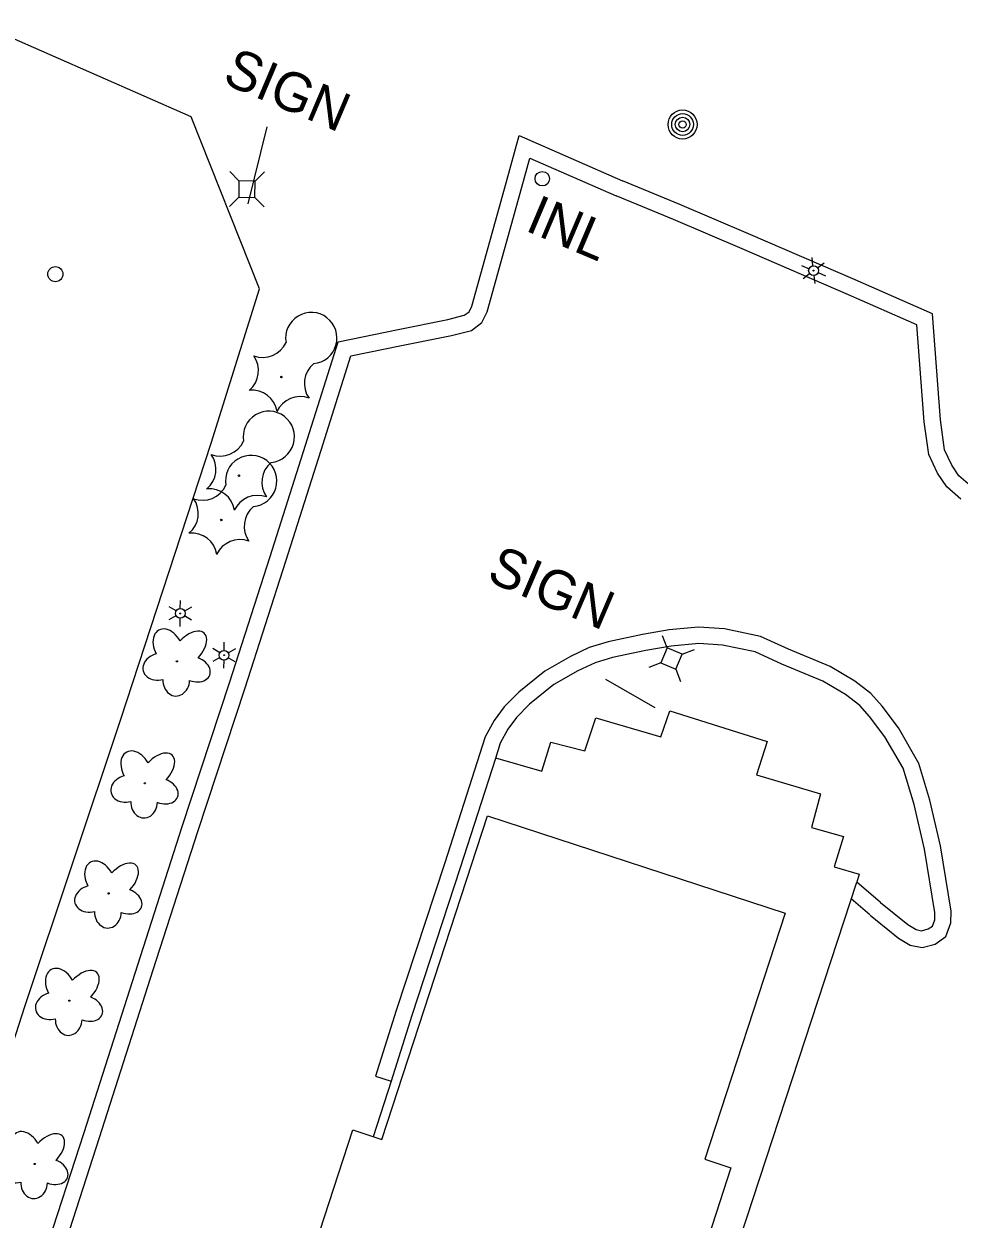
# Model space of a CAD drawing. Extents: x 588843 to 2552415, y 180129 to 269402.
# Drawn here: x 593101.4 to 593244.8, y 185579.7 to 185762.9 of the extents above; entities that cross this region are included whole.
import ezdxf

# ---------------------------------------------------------------- set-up
doc = ezdxf.new("R2010")
doc.units = 0
for name, color, linetype in [('Default', 7, 'Continuous'), ('E_BLD', 7, 'Continuous'), ('E_DRN', 7, 'Continuous'), ('E_DRN_Text', 7, 'Continuous'), ('E_DWY', 7, 'Continuous'), ('E_LAND_Vegetation', 7, 'Continuous'), ('E_LTG', 7, 'Continuous'), ('E_MISCPROP', 7, 'Continuous'), ('E_PATH_Sidewalk', 7, 'Continuous'), ('E_SGN', 7, 'Continuous'), ('E_SGN_Text', 7, 'Continuous'), ('E_UTL_AG_Bold', 7, 'Continuous')]:
    doc.layers.add(name, color=color, linetype=linetype)

# ---------------------------------------------------------------- blocks, each defined once
blk = doc.blocks.new('LPOL')
at = {"layer": 'Default'}
for p, q in [((-4, 0), (-1.5, 0)), ((-0.75, 1.3), (-2, 3.46)), ((0.75, 1.3), (2, 3.46)), ((1.5, 0), (4, 0)), ((-2, -3.46), (-0.75, -1.3)), ((2, -3.46), (0.75, -1.3))]:
    blk.add_line(p, q, dxfattribs=at)
for radius in [1.5, 1.5, 1.5, 0.125]:
    blk.add_circle((0, 0), radius, dxfattribs=at)
blk = doc.blocks.new('POLE')
at = {"layer": 'Default'}
for radius in [4.46, 3.35, 2.23, 1.12]:
    blk.add_circle((0, 0), radius, dxfattribs=at)
blk = doc.blocks.new('DTRE')
at = {"layer": 'Default'}
blk.add_circle((-0.18, 0), 0.183, dxfattribs=at)
for centre, major_axis, ratio in [((-1.87, 5.32), (1.36, -4.98), 0.782863), ((4.06, 2.74), (-5.27, -2.93), 0.691916), ((-5.87, 0.15), (4.93, -0.12), 0.832022), ((3.54, -3.71), (-5.01, 4.58), 0.560249), ((-2.49, -5.24), (1.8, 4.86), 0.716896)]:
    blk.add_ellipse(centre, major_axis=major_axis, ratio=ratio, start_param=1.570796, end_param=4.712389, dxfattribs=at)
blk = doc.blocks.new('CTRE')
at = {"layer": 'Default'}
blk.add_circle((0, 0), 0.223, dxfattribs=at)
for centre, start, end in [((-11.97, 8.96), 280.2067, 5.9716), ((1.81, 14.92), 220.2113, 305.9762), ((13.83, 5.89), 160.2113, 245.9762), ((-13.83, -5.9), 340.2113, 65.9762), ((12.03, -9.04), 185.9272, 100.2511), ((-1.81, -14.93), 40.2113, 125.9762)]:
    blk.add_arc(centre, 7.87, start, end, dxfattribs=at)
blk = doc.blocks.new('PED')
at = {"layer": 'Default'}
for p, q in [((-2.5, 2.5), (-5.33, 5.33)), ((2.5, 2.5), (5.33, 5.33)), ((-2.5, -2.5), (-5.33, -5.33)), ((2.5, -2.5), (5.33, -5.33))]:
    blk.add_line(p, q, dxfattribs=at)
blk.add_lwpolyline([(-2.5, -2.5), (2.5, -2.5), (2.5, 2.5), (-2.5, 2.5)], close=True, dxfattribs=at)
blk = doc.blocks.new('SIGN')
at = {"layer": 'Default'}
blk.add_text('SIGN', height=12, dxfattribs=at).set_placement((-18.55, -6))
blk = doc.blocks.new('INLT_41')
at = {"layer": 'E_DRN_Text'}
blk.add_text('INL', height=12, dxfattribs=at).set_placement((-11.03, -6))

msp = doc.modelspace()

# ---------------------------------------------------------------- linework, layer by layer
at = {"layer": 'E_BLD'}
msp.add_lwpolyline([(593172.43, 185641.5), (593218.07, 185626.6), (593205.76, 185588.9), (593209.78, 185587.59), (593205.14, 185573.36), (593201.06, 185574.69), (593188.55, 185536.35), (593183.23, 185538.09), (593178.68, 185524.15), (593161.23, 185529.85), (593165.83, 185543.96), (593141.48, 185551.91), (593148.16, 185572.38), (593145.24, 185573.33), (593151.78, 185593.37), (593156.24, 185591.91), (593172.43, 185641.5)], close=True, dxfattribs=at)
at = {"layer": 'E_DRN'}
for centre, radius in [((593180.85, 185739.19), 1.11), ((593106.19, 185724.56), 1.16)]:
    msp.add_circle(centre, radius, dxfattribs=at)
at = {"layer": 'E_DWY'}
for points in [[(593073.08, 185519.95), (593085.72, 185563.37), (593101.57, 185612.44), (593116.25, 185656.35), (593130.07, 185698.66), (593137.48, 185722.33), (593127, 185748.67), (593098.2, 185761.32), (593068.93, 185774.26), (593037.36, 185788.12), (593004.66, 185802.42), (592980.13, 185813.54), (592966.01, 185781.91), (592962.98, 185775.38), (592961.51, 185773.47), (592960.45, 185773.06), (592958.78, 185772.92), (592956.88, 185773.45), (592953.94, 185774.8), (592950.49, 185776.9)], [(593099.66, 185558.64), (593104.55, 185574.28), (593110.6, 185592.99), (593118.81, 185618.67), (593125.63, 185639.88), (593132.9, 185661.93), (593139.15, 185681.3), (593144.55, 185698.36), (593149.57, 185714.18), (593158.77, 185716.06), (593166.35, 185717.61), (593168.89, 185718.25), (593169.64, 185718.79), (593170.07, 185719.66), (593175.31, 185738.56), (593177.28, 185745.82), (593193.15, 185738.86)], [(593096.04, 185539.11), (593102.05, 185557.89), (593106.93, 185573.52), (593112.98, 185592.23), (593121.19, 185617.91), (593128.01, 185639.11), (593135.28, 185661.15), (593141.53, 185680.54), (593146.93, 185697.6), (593151.51, 185712.02), (593159.27, 185713.61), (593166.91, 185715.17), (593169.97, 185715.94), (593171.6, 185717.13), (593172.41, 185718.76), (593177.72, 185737.9), (593178.93, 185742.36), (593192.2, 185736.55)], [(593246.52, 185692.09), (593244.74, 185693.64), (593243.62, 185695.28), (593242.54, 185697.61), (593241.89, 185702.21), (593240.68, 185718.47), (593228.82, 185723.69), (593212.46, 185730.72), (593201.96, 185735.22), (593193.15, 185738.86)], [(593245.04, 185690.06), (593242.85, 185691.97), (593241.44, 185694.05), (593240.11, 185696.9), (593239.41, 185701.94), (593238.3, 185716.79), (593227.82, 185721.4), (593211.47, 185728.42), (593200.99, 185732.92), (593192.2, 185736.55)], [(593238.56, 185649.54), (593235.45, 185655.01), (593232.96, 185658.34), (593231.23, 185660.26), (593228.76, 185662.18), (593224.98, 185664.42), (593218.58, 185667.07), (593214.28, 185669.03), (593208.81, 185670.18), (593204.8, 185670.45), (593200.28, 185670.02), (593196.23, 185669.33), (593190.97, 185668.21), (593188.05, 185667.31), (593185.15, 185665.96), (593181.22, 185663.71), (593177.23, 185660.5), (593175.01, 185658.24), (593173.47, 185656.16), (593172.08, 185653.64), (593171.27, 185651.07), (593165.91, 185634.32), (593158.46, 185611.69), (593155.29, 185601.6)], [(593236.17, 185648.81), (593233.37, 185653.61), (593231.03, 185656.75), (593229.52, 185658.43), (593227.35, 185660.11), (593223.86, 185662.18), (593217.59, 185664.78), (593213.49, 185666.64), (593208.47, 185667.69), (593204.83, 185667.94), (593200.61, 185667.54), (593196.7, 185666.87), (593191.6, 185665.79), (593188.95, 185664.97), (593186.3, 185663.74), (593182.64, 185661.64), (593178.91, 185658.65), (593176.91, 185656.61), (593175.58, 185654.8), (593174.39, 185652.65), (593173.66, 185650.32), (593168.28, 185633.55), (593160.84, 185610.92), (593157.68, 185600.85)], [(593231.1, 185626.32), (593235.44, 185622.79), (593237.27, 185621.72), (593239.07, 185621.36), (593241.07, 185621.87), (593242.74, 185623.02), (593243.51, 185625.11), (593243.54, 185626.9), (593241.89, 185636.92), (593240.27, 185643.93), (593238.56, 185649.54)], [(593232.68, 185628.26), (593236.87, 185624.85), (593238.17, 185624.09), (593239, 185623.92), (593240.02, 185624.18), (593240.67, 185624.62), (593241.01, 185625.58), (593241.04, 185626.72), (593239.44, 185636.43), (593237.85, 185643.28), (593236.17, 185648.81)], [(593176.8, 185473.48), (593189.83, 185511.82), (593203.12, 185552.15), (593220.18, 185604.24), (593229.08, 185631.35)], [(593232.68, 185628.26), (593229.08, 185631.35)], [(593231.05, 185626.36), (593228.23, 185628.78)], [(593155.29, 185601.6), (593157.68, 185600.85), (593154.94, 185592.34)]]:
    msp.add_lwpolyline(points, dxfattribs=at)
at = {"layer": 'E_PATH_Sidewalk'}
msp.add_lwpolyline([(593173.69, 185650.43), (593180.8, 185648.37), (593182.15, 185652.81), (593187.38, 185651.51), (593189.04, 185656.55), (593199.02, 185653.64), (593200.42, 185657.62), (593215.33, 185652.92), (593213.7, 185647.8), (593223.48, 185644.92), (593222.1, 185639.74), (593227.03, 185638.38), (593225.59, 185633.7), (593229.42, 185632.57), (593229.08, 185631.35)], dxfattribs=at)
at = {"layer": 'E_SGN'}
for points in [[(593135.76, 185735.33), (593138.65, 185747.16)], [(593198.18, 185658.1), (593190.57, 185662.41)]]:
    msp.add_lwpolyline(points, dxfattribs=at)

# ---------------------------------------------------------------- block references
at = {"layer": 'E_DRN_Text', "xscale": 0.4999999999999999, "yscale": 0.5, "rotation": -22.99539777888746}
msp.add_blockref('INLT_41', (593184.29, 185731.92), dxfattribs=at)
at = {"layer": 'E_LAND_Vegetation', "xscale": 0.5000000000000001, "yscale": 0.5, "rotation": 89.39188762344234}
for name, p in [('CTRE', (593140.85, 185708.79)), ('CTRE', (593134.33, 185693.66)), ('CTRE', (593131.62, 185686.88)), ('DTRE', (593124.83, 185665.29)), ('DTRE', (593119.91, 185646.6)), ('DTRE', (593114.36, 185629.72)), ('DTRE', (593108.34, 185613.27)), ('DTRE', (593103.03, 185588.25))]:
    msp.add_blockref(name, p, dxfattribs=at)
at = {"layer": 'E_LTG'}
for p, xscale, yscale, rotation in [((593222.44, 185725.1), 0.4999999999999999, 0.4999999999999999, -23.35379701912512), ((593125.34, 185672.55), 0.5000000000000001, 0.5, 89.39188762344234), ((593132.06, 185666.14), 0.5000000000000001, 0.5, 89.39188762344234)]:
    msp.add_blockref('LPOL', p, dxfattribs=dict(at, xscale=xscale, yscale=yscale, rotation=rotation))
at = {"layer": 'E_MISCPROP', "xscale": 0.4999999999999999, "yscale": 0.4999999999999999, "rotation": -23.35379701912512}
msp.add_blockref('POLE', (593202.36, 185747.5), dxfattribs=at)
at = {"layer": 'E_SGN_Text', "yscale": 0.5}
for p, xscale, rotation in [((593141.32, 185753.05), 0.4999999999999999, -22.99539777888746), ((593181.82, 185676.74), 0.5, -23.24621857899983)]:
    msp.add_blockref('SIGN', p, dxfattribs=dict(at, xscale=xscale, rotation=rotation))
at = {"layer": 'E_UTL_AG_Bold', "yscale": 0.5}
for p, xscale, rotation in [((593135.56, 185737.58), 0.5000000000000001, 89.39188762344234), ((593200.66, 185665.64), 0.5, -23.24621857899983)]:
    msp.add_blockref('PED', p, dxfattribs=dict(at, xscale=xscale, rotation=rotation))

doc.saveas('drawing.dxf')
